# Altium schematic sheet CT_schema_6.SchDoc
size 218 x 258 mm
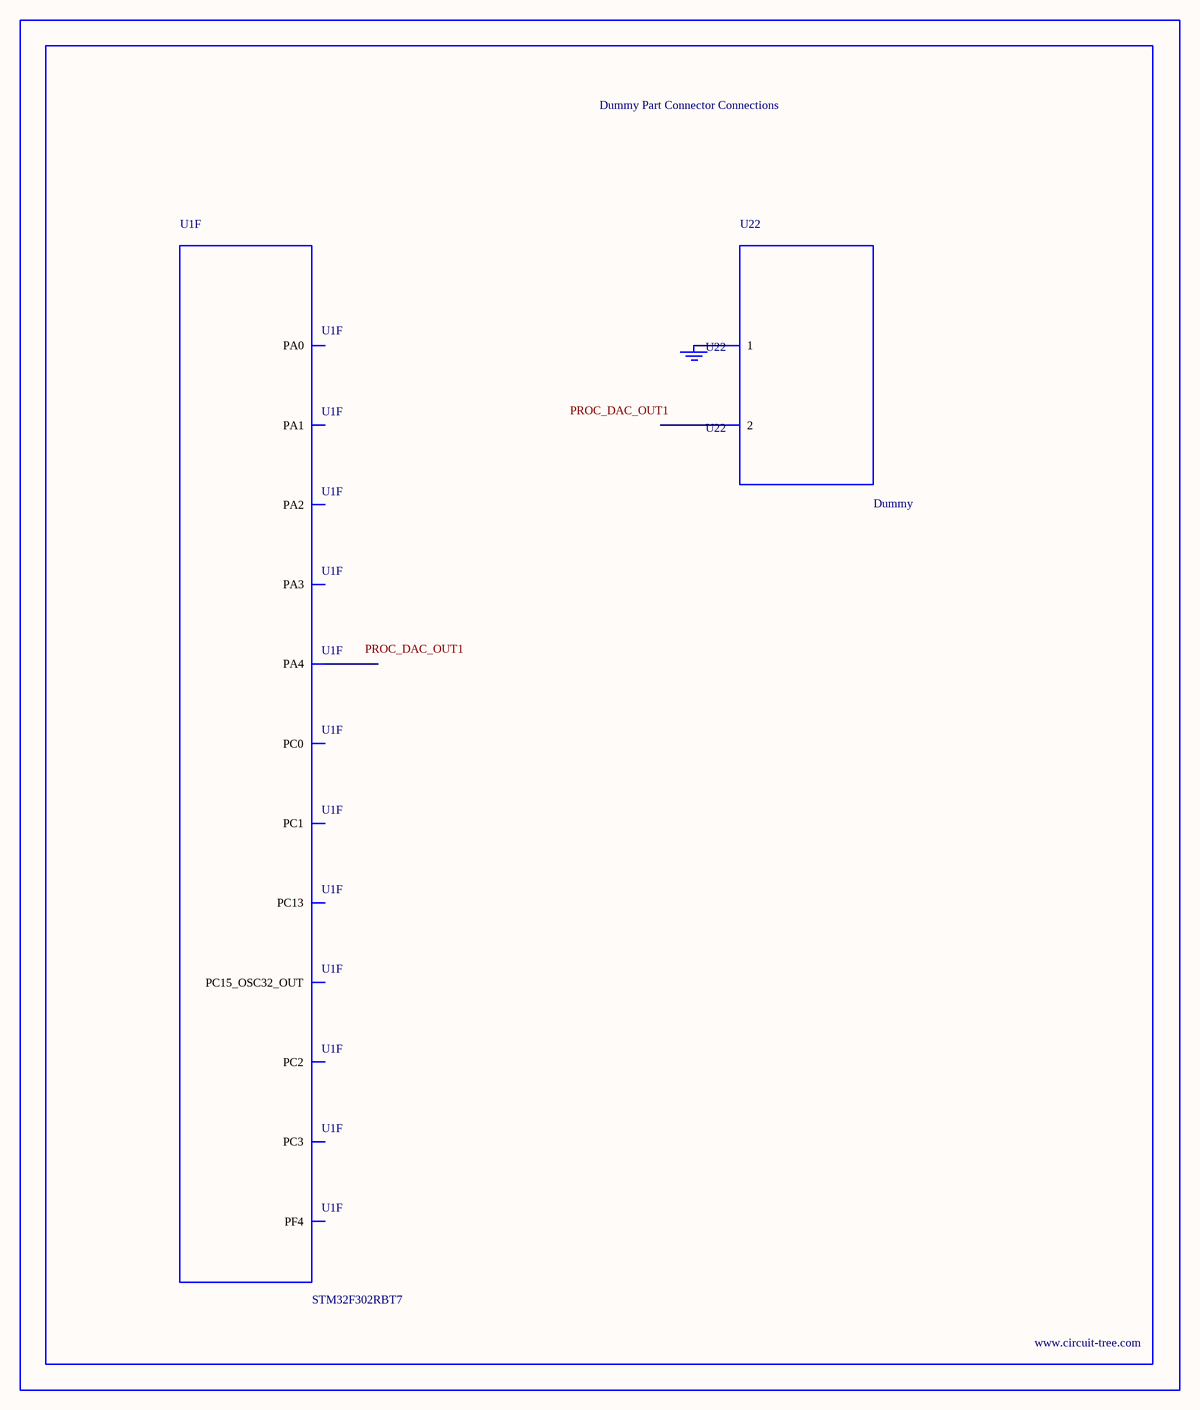
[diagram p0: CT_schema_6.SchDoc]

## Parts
BORDER5  (no value)
GND_INSTANCE_5_0  (no value)
U1  STM32F302RBT7  [LQFP64]  (part F of 6)
U22  Dummy  [DUMMY_PACKAGE_184]

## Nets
NetGND_INSTANCE_5_0_0: GND_INSTANCE_5_0.0(GND) U22.1

Not connected (* = marked no-connect by the designer): U1 2(PC13) 4(PC15_OSC32_OUT) 8(PC0) 9(PC1) 10(PC2) 11(PC3) 14(PA0) 15(PA1) 16(PA2) 17(PA3) 18(PF4) 20(PA4); U22 2

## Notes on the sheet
- Labels drawn without touching a wire or pin: PROC_DAC_OUT1

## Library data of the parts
BORDER5 = BORDER_PAGE5
GND_INSTANCE_5_0 = GND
